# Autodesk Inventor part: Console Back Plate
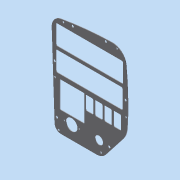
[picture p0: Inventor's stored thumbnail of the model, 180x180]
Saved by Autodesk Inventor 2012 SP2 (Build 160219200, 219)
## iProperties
Created: 2016-05
Part Number: Console Back Plate
Material: Default
Document SubType Name: Modeling
Designer: Bob
Density: 1 g/cm^3
Author: Bob
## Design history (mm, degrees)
sketch "Sketch1"
  geometry: L1 (-25.315, 224.563)-(-17.452, -0.609); L2 (0, -17.463)-(-0.175, -17.462); L3 (122.383, -5.504)-(170.686, 56.322); L4 (0, -17.463)-(97.864, -17.463); L5 (182.954, 144.067)-(182.954, 284.471); A1 r 17.463 centre (0, 0) between (-17.452, -0.609) and (0, -17.463); A2 r 31.115 centre (97.864, 13.653) between (97.864, -17.463) and (122.383, -5.504); A3 r 50.8 centre (130.656, 87.597) between (170.686, 56.322) and (181.369, 84.638); A4 r 38.1 centre (140.092, 231.216) between (177.989, 235.141) and (139.132, 269.303); A5 r 30.163 centre (4.829, 225.615) between (-0.409, 255.32) and (-25.315, 224.563); A6 r 939.8 centre (162.811, -670.198) between (139.132, 269.303) and (-0.409, 255.32); A7 r 933.208 centre (-750.254, 139.003) between (181.369, 84.638) and (177.989, 235.141); 1 further point
  constraints: 15 point on circle, 13 tangent, 10 end point, 7 centre point, 1 coincident, 1 horizontal, 1 perpendicular
  dimensions: "d3" = 34.925 diameter of A1; "d4" = 62.23 diameter of A2; "d5" = 101.6 diameter of A3; "d6" = 76.2 diameter of A4; "d7" = 60.325 diameter of A5; "d9" = 939.8 radius of A6; "d11" = 115.316 horizontal distance of A2.centre L1.end; "d12" = 148.1074 horizontal distance of A3.centre L1.end; "d24" = 243.078 distance from line of A5.centre L4; "d25" = 286.766 distance from line of L4 A4.end; "d26" = 92 deg angle of L4 L1; "d27" = 52 deg angle of L4 L3; "d60" = 42.8625 distance from line of L5 A4.centre; "d70" = 200.406 distance from line of L1.end L5; "d71" = 130.79586 distance from line of L5.end L3; "d72" = 44.3543 distance from line of L5.start L3; "d73" = 183.12865 distance from line of L2.end L5
extrude "Extrusion1" new body sketch "Sketch1" distance "d30" = 1.524; taper "d31" = 0 deg
sketch "Sketch2"
  geometry: C1 r 15.875 at (29.21, 19.05); C2 r 1.984 at (49.53, 19.05); C3 r 1.984 at (8.89, 19.05); C4 r 2.54 at (-6.35, -11.113); C5 r 2.54 at (-16.51, 109.22); C6 r 2.54 at (6.35, 250.825); C7 r 2.54 at (153.162, 261.62); C8 r 2.54 at (177.8, 111.125); C9 r 2.54 at (109.525, -6.985); C10 r 11.113 at (104.14, 19.558); A1 r 17.463 centre (0, 0) between (-17.452, -0.609) and (0, -17.463) reference
  constraints: 10 centre point, 6 equal radius
  dimensions: "d32" = 40.64 distance of C2.centre C3.centre; "d33" = 0 vertical distance of C1.centre C3.centre; "d34" = 0 vertical distance of C3.centre C2.centre; "d35" = 20.32 distance of C1.centre C3.centre (= 0.5 x d32); "d36" = 3.96875 diameter of C2; "d37" = 31.75 diameter of C1; "d38" = 29.21 horizontal distance of C1.centre A1.centre; "d39" = 19.05 vertical distance of C1.centre A1.centre; "d40" = 6.35 horizontal distance of C4.centre A1.centre; "d41" = 5.08 diameter of C9; "d42" = 11.1125 vertical distance of C4.centre A1.centre; "d44" = 6.985 vertical distance of C9.centre A1.centre; "d45" = 109.5248 horizontal distance of C9.centre A1.centre; "d46" = 22.225 diameter of C10; "d47" = 19.558 vertical distance of C10.centre A1.centre; "d48" = 104.14 horizontal distance of C10.centre A1.centre; "d49" = 177.8 horizontal distance of C8.centre A1.centre; "d50" = 111.125 vertical distance of A1.centre C8.centre; "d51" = 109.22 vertical distance of A1.centre C5.centre; "d52" = 16.51 horizontal distance of A1.centre C5.centre; "d53" = 250.825 vertical distance of A1.centre C6.centre; "d54" = 6.35 horizontal distance of C6.centre A1.centre; "d55" = 153.162 horizontal distance of C7.centre A1.centre; "d56" = 261.62 vertical distance of C7.centre A1.centre
extrude "Extrusion2" cut sketch "Sketch2" stored distance "d57" = 25.4; taper "d58" = 0 deg
sketch "Sketch3"
  geometry: L1 (166.599, 185.738)-(-10.389, 185.737); L2 (170.18, 236.258)-(170.18, 189.319); L3 (-10.389, 177.038)-(165.329, 177.038); L4 (168.91, 173.457)-(168.91, 126.517); L5 (165.329, 122.936)-(-10.389, 122.936); L6 (-13.97, 126.517)-(-13.97, 173.457); L7 (-1.651, 111.379)-(62.611, 111.379); L8 (64.135, 109.855)-(64.135, 40.513); L9 (62.611, 38.989)-(-1.651, 38.989); L10 (-3.175, 40.513)-(-3.175, 109.855); L11 (70.485, 110.109)-(85.344, 110.109); L12 (88.519, 106.934)-(88.519, 75.438); L13 (85.344, 72.263)-(70.485, 72.263); L14 (67.31, 75.438)-(67.31, 106.934); L15 (95.885, 110.109)-(110.744, 110.109); L16 (113.919, 106.934)-(113.919, 75.438); L17 (110.744, 72.263)-(95.885, 72.263); L18 (92.71, 75.438)-(92.71, 106.934); L19 (121.285, 110.109)-(136.144, 110.109); L20 (139.319, 106.934)-(139.319, 75.438); L21 (136.144, 72.263)-(121.285, 72.263); L22 (118.11, 75.438)-(118.11, 106.934); L23 (146.685, 110.109)-(161.544, 110.109); L24 (164.719, 106.934)-(164.719, 75.438); L25 (161.544, 72.263)-(146.685, 72.263); L26 (143.51, 75.438)-(143.51, 106.934); L27 (-13.97, 236.258)-(-13.97, 189.319); L28 (-10.389, 239.839)-(166.599, 239.839); A1 r 17.463 centre (0, 0) between (-17.452, -0.609) and (0, -17.463) reference; A2 r 3.581 centre (-10.389, 236.258) between (-10.389, 239.839) and (-13.97, 236.258); A3 r 3.581 centre (-10.389, 189.319) between (-13.97, 189.319) and (-10.389, 185.737); A4 r 3.581 centre (166.599, 189.319) between (166.599, 185.738) and (170.18, 189.319); A5 r 3.581 centre (166.599, 236.258) between (170.18, 236.258) and (166.599, 239.839); A6 r 3.581 centre (-10.389, 173.457) between (-10.389, 177.038) and (-13.97, 173.457); A7 r 3.581 centre (-10.389, 126.517) between (-13.97, 126.517) and (-10.389, 122.936); A8 r 3.581 centre (165.329, 126.517) between (165.329, 122.936) and (168.91, 126.517); A9 r 3.581 centre (165.329, 173.457) between (168.91, 173.457) and (165.329, 177.038); A10 r 3.175 centre (70.485, 106.934) between (70.485, 110.109) and (67.31, 106.934); A11 r 3.175 centre (70.485, 75.438) between (67.31, 75.438) and (70.485, 72.263); A12 r 3.175 centre (85.344, 75.438) between (85.344, 72.263) and (88.519, 75.438); A13 r 3.175 centre (85.344, 106.934) between (88.519, 106.934) and (85.344, 110.109); A14 r 3.175 centre (95.885, 106.934) between (95.885, 110.109) and (92.71, 106.934); A15 r 3.175 centre (110.744, 106.934) between (113.919, 106.934) and (110.744, 110.109); A16 r 3.175 centre (110.744, 75.438) between (110.744, 72.263) and (113.919, 75.438); A17 r 3.175 centre (95.885, 75.438) between (92.71, 75.438) and (95.885, 72.263); A18 r 3.175 centre (121.285, 106.934) between (121.285, 110.109) and (118.11, 106.934); A19 r 3.175 centre (121.285, 75.438) between (118.11, 75.438) and (121.285, 72.263); A20 r 3.175 centre (136.144, 75.438) between (136.144, 72.263) and (139.319, 75.438); A21 r 3.175 centre (136.144, 106.934) between (139.319, 106.934) and (136.144, 110.109); A22 r 3.175 centre (146.685, 106.934) between (146.685, 110.109) and (143.51, 106.934); A23 r 3.175 centre (146.685, 75.438) between (143.51, 75.438) and (146.685, 72.263); A24 r 3.175 centre (161.544, 75.438) between (161.544, 72.263) and (164.719, 75.438); A25 r 3.175 centre (161.544, 106.934) between (164.719, 106.934) and (161.544, 110.109); A26 r 1.524 centre (-1.651, 109.855) between (-1.651, 111.379) and (-3.175, 109.855); A27 r 1.524 centre (62.611, 109.855) between (64.135, 109.855) and (62.611, 111.379); A28 r 1.524 centre (62.611, 40.513) between (62.611, 38.989) and (64.135, 40.513); A29 r 1.524 centre (-1.651, 40.513) between (-3.175, 40.513) and (-1.651, 38.989)
  constraints: 56 end point, 56 point on circle, 56 tangent, 28 centre point, 25 equal radius, 13 parallel, 7 collinear, 7 horizontal, 7 perpendicular, 4 equal length
  dimensions: "d75" = 3.175 radius of A10; "d76" = 1.524 radius of A26; "d78" = 13.97 distance from line of L27 A1.centre; "d79" = 184.15 distance between parallel lines of L2 L27; "d80" = 3.5814 radius of A2; "d81" = 182.88 distance between parallel lines of L6 L4; "d82" = 54.102 distance between parallel lines of L5 L3; "d83" = 185.7375 distance from line of L1 A1.centre; "d84" = 122.936 distance from line of L5 A1.centre; "d85" = 37.846 distance between parallel lines of L25 L23; "d86" = 72.263 distance from line of A1.centre L25; "d87" = 21.209 distance between parallel lines of L24 L26; "d88" = 67.31 distance from line of L14 A1.centre; "d89" = 25.4 distance between parallel lines of L18 L14; "d90" = 25.4 distance between parallel lines of L22 L18 (derived); "d91" = 25.4 distance between parallel lines of L26 L22 (derived); "d92" = 72.39 distance between parallel lines of L9 L7; "d93" = 111.379 distance from line of A1.centre L7; "d94" = 3.175 distance from line of A1.centre L10; "d95" = 67.31 distance between parallel lines of L10 L8
extrude "Extrusion3" cut sketch "Sketch3" distance "d96" = 25.4; taper "d97" = 0 deg
sketch "Sketch4"
  geometry: C1 r 3.175 at (31.75, 254); C2 r 3.175 at (122.428, 262.89); C3 r 3.175 at (176.53, 151.13); C4 r 3.175 at (132.08, 17.78); C5 r 3.175 at (-11.43, 16.51); C6 r 3.175 at (-17.78, 147.32); A1 r 17.463 centre (0, 0) between (-17.452, -0.609) and (0, -17.463) reference
  constraints: 6 centre point, 5 equal radius
  dimensions: "d98" = 16.51 vertical distance of C5.centre A1.centre; "d99" = 6.35 diameter of C4; "d100" = 11.43 horizontal distance of A1.centre C5.centre; "d101" = 147.32 vertical distance of A1.centre C6.centre; "d102" = 17.78 horizontal distance of A1.centre C6.centre; "d103" = 254 vertical distance of A1.centre C1.centre; "d104" = 31.75 horizontal distance of A1.centre C1.centre; "d105" = 262.89 vertical distance of A1.centre C2.centre; "d106" = 122.428 horizontal distance of C2.centre A1.centre; "d107" = 151.13 vertical distance of A1.centre C3.centre; "d108" = 176.53 horizontal distance of A1.centre C3.centre; "d109" = 17.78 vertical distance of C4.centre A1.centre; "d110" = 132.08 horizontal distance of A1.centre C4.centre
extrude "Extrusion4" cut sketch "Sketch4" stored distance "d111" = 25.4; taper "d112" = 0 deg
body "Solid1"
